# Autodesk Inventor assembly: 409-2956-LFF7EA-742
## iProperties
Created: 2010-09
Part Number: 409-2956-LFF7EA-742
Document SubType Name: Weldment
Designer: S. Boerckel
Weld Material: Welded Steel Mild
Mass: 27650.6 g
Surface Area: 9578.63 cm^2
Volume: 3515.61 cm^3
Density: 7.86509 g/cm^3
Description: DISCHARGE SPOOL
User Status: WELD
Material: WELDMENT
SMR: =<MATERIAL>
Author: S. Boerckel
Revision Number: A
